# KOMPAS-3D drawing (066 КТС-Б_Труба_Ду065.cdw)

Referenced files: Graphic.tdp
Referenced files in D:\100_Работа\003_КД\003_Проекты\СхемыУстПриборов\: КТС-Б_Труба_Ду100.cdw
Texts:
  ПСПД-0000-2015
  Узел коммерческого учёта тепловой энергии
  Кремляков А.И.
  Служба проектно-сметная
  ПромСервисА.И.
  Лит-Масса-Масштаб
  Материал-Предприятие
  Title Specification
  Body Specification ( left align )
  Body Specificaton ( centered )
  ГОСТ 16037-80-У20-ЗН- 3
  *Размеры для справок.
  Допустимое   угловое  смещение   деталей поз.1, 2, 3
  относительно фланцев и номинального положения  2 .
  Сварные швы проверить внешним осмотром по ГОСТ 3242-79.
  Трещины, прожоги, свищи, раковины, непровары не допускаются.
  Измерительный участок испытать на прочность и
  герметичность пробным гидравлическим давлением Pпр=2,0 МПа в
  течение 30 мин. Течь, потение, видимые остаточные деформации не
  допускаются.
  Термометр сопротивления поз.1 и выступающие части бобышки
  поз.2 и гильзы поз.3 изолировать на высоту 50...60 мм трубчатой
  теплоизоляцией  1/2"; S=13 мм, закрепив её лентой самоклеещей.
  ООО "ПОИНТ"
  Tермометр
  сопротивления
  платиновый КТС-Б
  Pt100-A-х4-П-2-
  Tермометр  / сопротивления  / платиновый КТС-Б / Pt100-A-х4-П-2- / 120/4-Ж
  один из
  компл.
  один из компл.
  СДФИ.408727.001-21
  ООО "ПОИНТ" СДФИ.408727.001-21
  Бобышка
  Бобышка 1/20-24-М12х1,5
  для
  КТС-Б
  для КТС-Б
  Гильза
  ГЦР.105-М12х1,5-6/4-
  Гильза  ГЦР.105-М12х1,5-6/4- 80-2,5
  Поз.
  Кол.
  Приме-
  чание
  Таблица спецификации
  Нач. отд.
  ЗАО "ПромСервис"
  г. Димитровград
  Узел коммерческого
  учёта тепловой энергии
  Установка
  термопреобразователя
  на трубу Ду65 (d76x5,5)
  ПСПД-0016-2014-
Dimensions and other numbers on the sheet: 80; 120; 50,5; 4; 6; 76; 65; 5,5; 1; 2; 3; 120/4-Ж; 1/20-24-М12х1,5; 80-2,5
